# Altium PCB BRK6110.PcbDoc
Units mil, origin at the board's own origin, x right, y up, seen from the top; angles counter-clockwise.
Board outline 4724.41 x 3149.61 mil, 2 copper layers (Top Layer, Bottom Layer), stack 64.8 mil thick; 19 components, 137 nets, 362 pads, 78 vias.
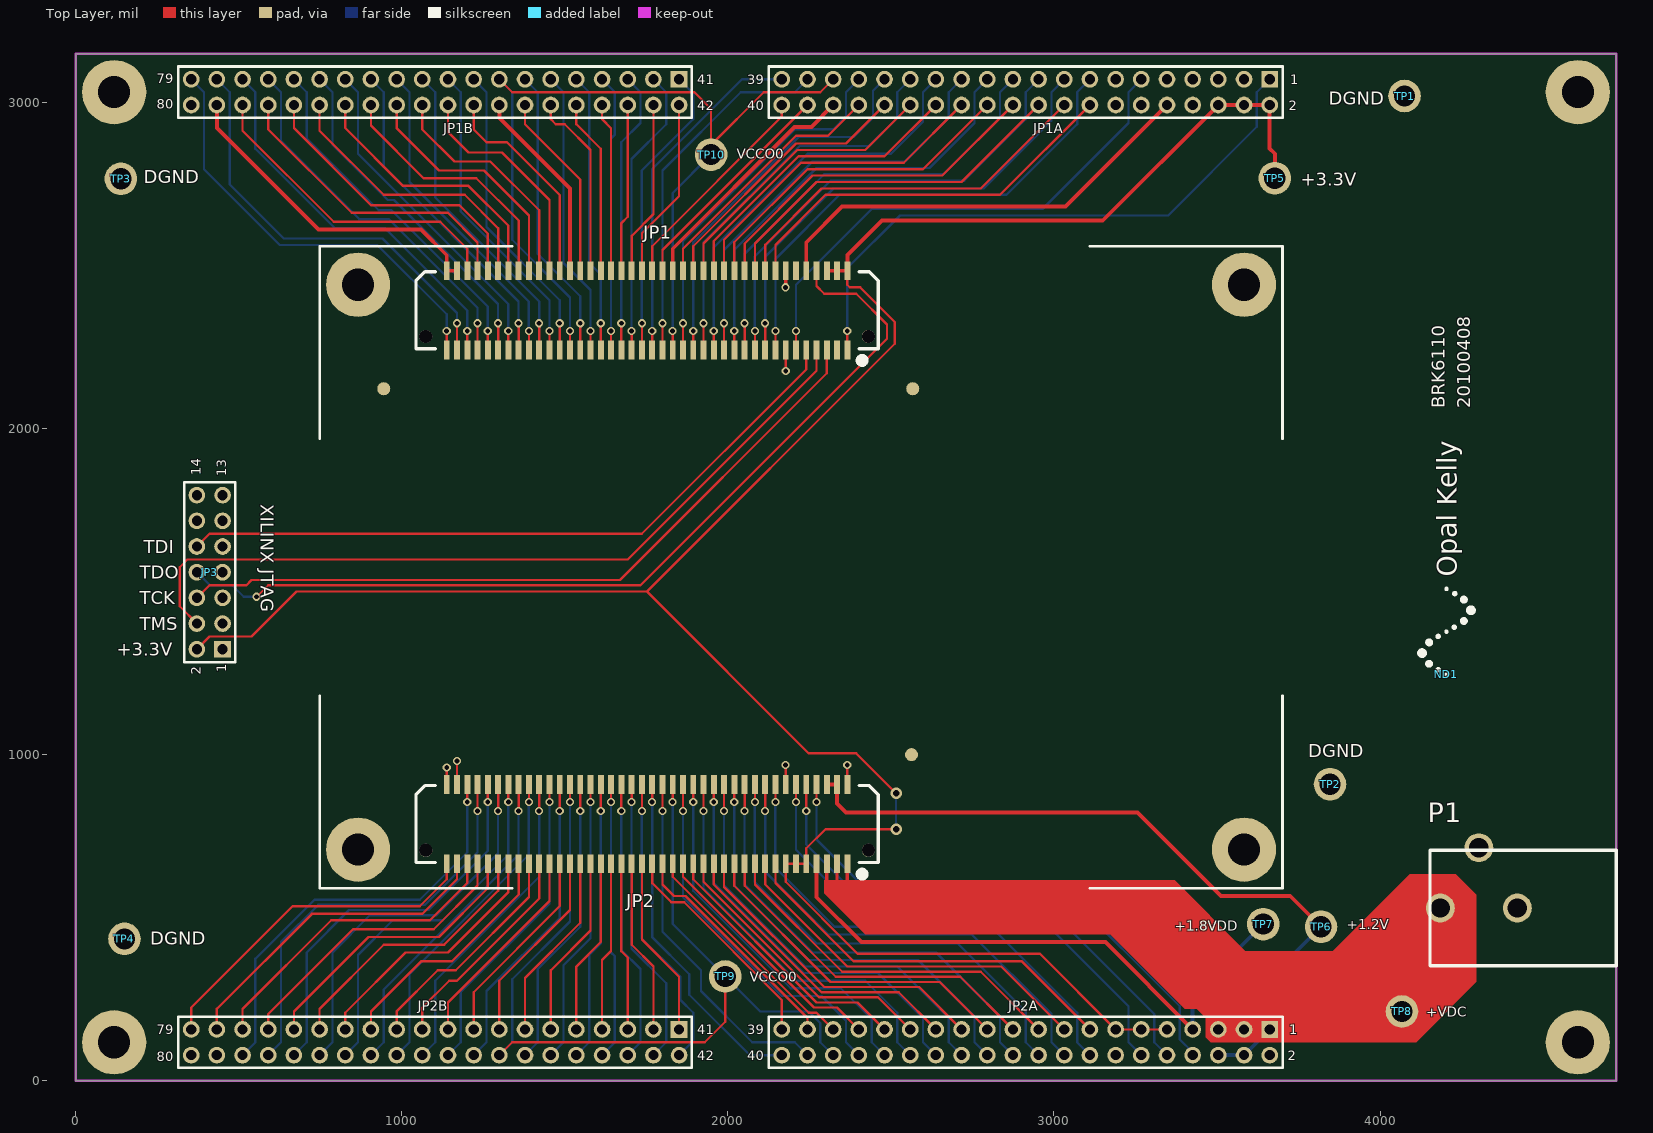
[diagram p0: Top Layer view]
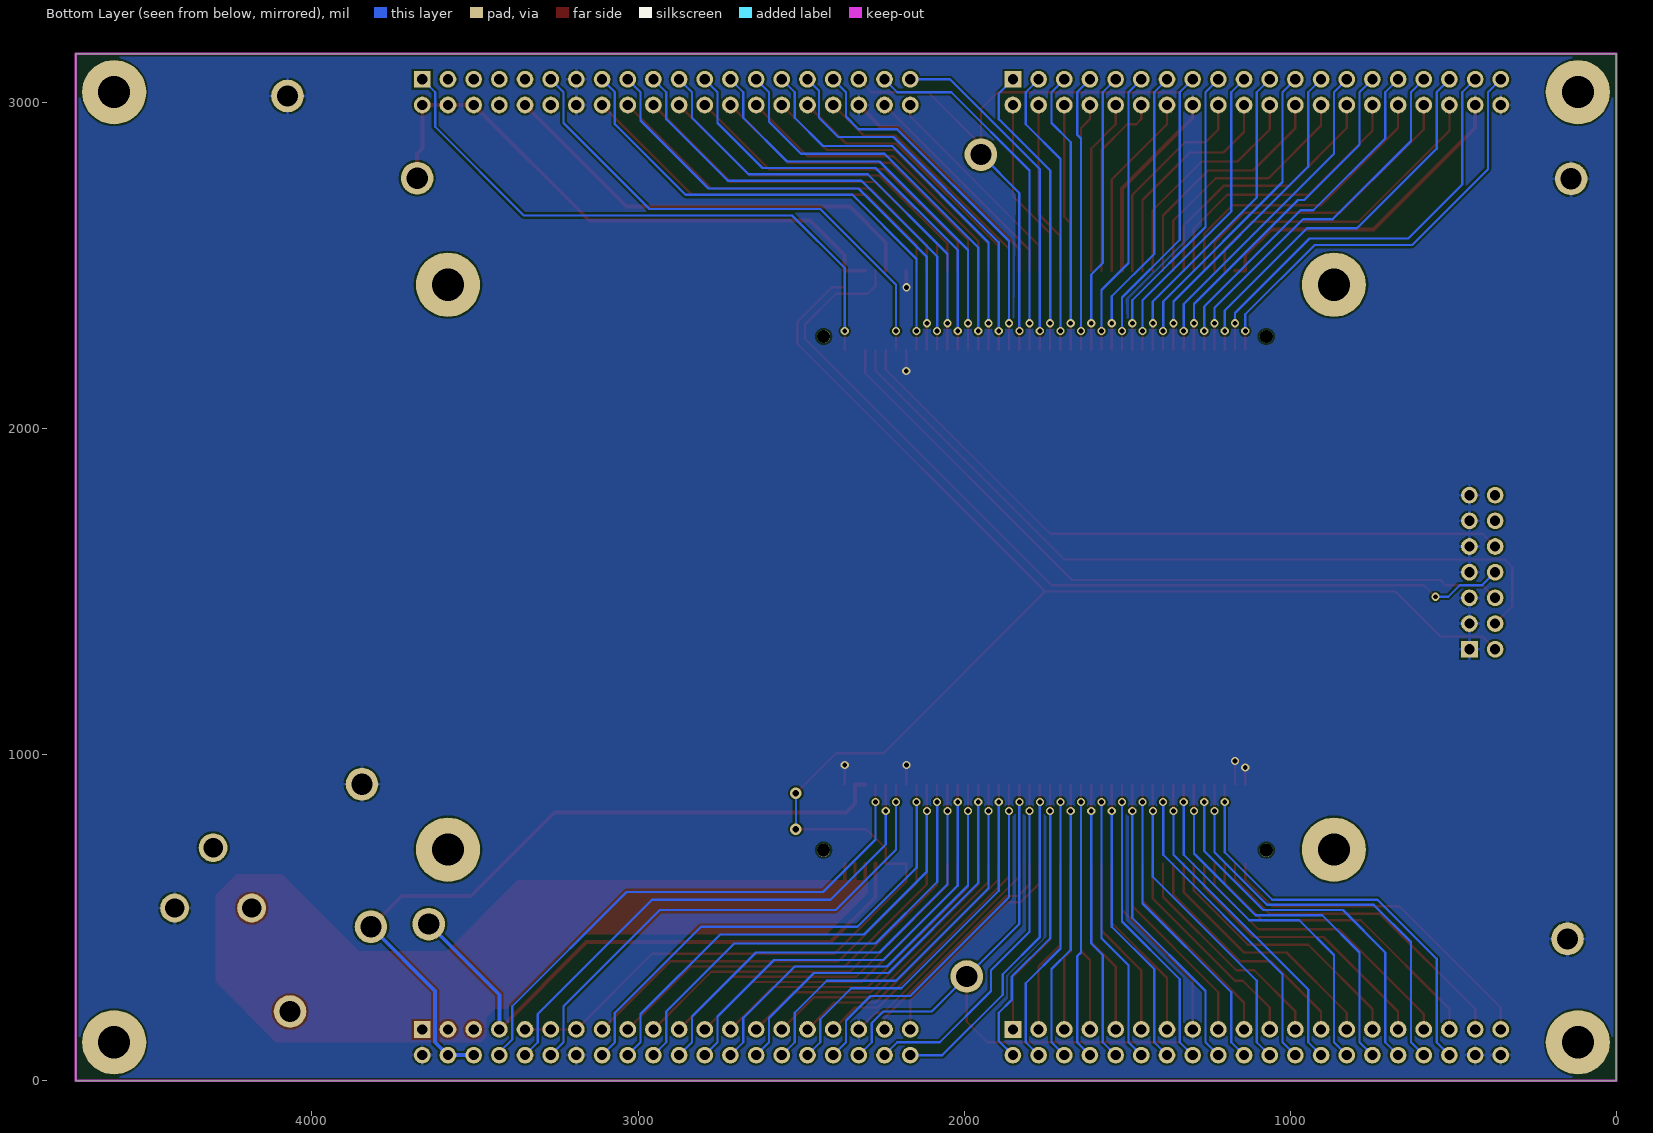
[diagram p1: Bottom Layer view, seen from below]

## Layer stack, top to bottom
Top Layer: signal copper 1.4
Dielectric: core 62, FR-4, Dk 4.8
Bottom Layer: signal copper 1.4

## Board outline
0,0 0,3149.61 4724.41,3149.61 4724.41,0

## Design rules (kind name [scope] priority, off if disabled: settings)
Clearance [All] p1: gap=6
FabricationTestPointUsage TestPointUsage [All] p1: valid=0 allowmultiple=FALSE
FabricationTestpoint Testpoint [All] p1: side=3 testpointundercomponent=TRUE minsize=40 maxsize=100 preferedsize=60 minholesize=0 maxholesize=40 preferedholesize=32 testpointgrid=1 allowsidetop=TRUE allowsidebottom=TRUE usegrid=TRUE gridtolerance=0.01
HoleSize [All] p1: absolutevalues=TRUE maxlimit=236.22 minlimit=15 maxpercent=80.000 minpercent=20.000
PolygonConnect "Via Connect" [IsVia] p1: connectstyle=Direct reliefconductorwidth=10 reliefentries=4 polygonreliefangle="90 Angle"
PolygonConnect [All] p2: connectstyle=Relief reliefconductorwidth=10 reliefentries=4 polygonreliefangle="90 Angle"
RoutingVias [All] p1: holewidth=15 width=25 viastyle="Through Hole" minholewidth=10 minwidth=20 maxholewidth=50 maxwidth=100
SilkscreenOverComponentPads [All] p1: minsilkscreentomaskgap=10
SolderMaskExpansion [All] p1: expansion=4
Width [All] p1: maxlimit=40 minlimit=6 preferedwidth=6 minimp=50.000000 maximp=50.000000 favimp=50.000000
24 further rules are at their usual default settings.

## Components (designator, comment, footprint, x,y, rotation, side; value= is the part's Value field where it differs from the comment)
JP1 "BTE/BSE-040" BTE-040 1752.17,2362.4 r180 top
JP1A "Header 20X2" HDR2X20-2MM 2913.39,3031.5 r180 top
JP1B "Header 20X2" HDR2X20-2MM 1102.36,3031.5 r180 top
JP2 "BTE/BSE-040" BTE-040 1752.17,787.2 r180 top
JP2A "Header 20X2" HDR2X20-2MM 2913.39,118.11 r180 top
JP2B "Header 20X2" HDR2X20-2MM 1102.36,118.11 r180 top
JP3 "JTAGXLNX" HDR2X7-2MM 411.18,1559.53 r90 top
ND1 "OKLOGO" oklogotiny 4203.47,1245.85 r90 top
P1 "DCPOWER" CUI-PJ102A 4723.94,529.61 r90 top
TP1 "TESTPOINT" TP_MED#1 4074.8,3019.69 r180 top
TP2 "TESTPOINT" TP_MED#1 3846.46,909.45 r180 top
TP3 "TESTPOINT" TP_MED#1 138.72,2765.68 r180 top
TP4 "TESTPOINT" TP_MED#1 149.81,435.09 r180 top
TP5 "TESTPOINT" TP_MED#1 3677.17,2767.72 r270 top
TP6 "TESTPOINT" TP_MED#2 3997.32,472.44 r180 top
TP7 "TESTPOINT" TP_MED#1 3641.73,480.31 r180 top
TP8 "TESTPOINT" TP_MED#1 4066.93,212.6 r180 top
TP9 "TESTPOINT" TP_MED#3 1980,320 r180 top
TP10 "TESTPOINT" TP_MED#4 1980,2840 r180 top

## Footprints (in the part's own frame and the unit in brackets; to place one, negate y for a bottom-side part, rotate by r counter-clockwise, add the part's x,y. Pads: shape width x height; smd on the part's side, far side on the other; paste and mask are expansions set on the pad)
BTE-040 [mm] "0.8mm Samtech socket"
  rect 0.46x1.45 smd: 1(-15.6,3.085) 2(-15.6,-3.085) 3(-14.8,3.085) 4(-14.8,-3.085) 5(-14,3.085) 6(-14,-3.085) 7(-13.2,3.085) 8(-13.2,-3.085) 9(-12.4,3.085) 10(-12.4,-3.085) 11(-11.6,3.085) 12(-11.6,-3.085) 13(-10.8,3.085) 14(-10.8,-3.085) 15(-10,3.085) 16(-10,-3.085) 17(-9.2,3.085) 18(-9.2,-3.085) 19(-8.4,3.085) 20(-8.4,-3.085) 21(-7.6,3.085) 22(-7.6,-3.085) 23(-6.8,3.085) 24(-6.8,-3.085) 25(-6,3.085) 26(-6,-3.085) 27(-5.2,3.085) 28(-5.2,-3.085) 29(-4.4,3.085) 30(-4.4,-3.085) 31(-3.6,3.085) 32(-3.6,-3.085) 33(-2.8,3.085) 34(-2.8,-3.085) 35(-2,3.085) 36(-2,-3.085) 37(-1.2,3.085) 38(-1.2,-3.085) 39(-0.4,3.085) 40(-0.4,-3.085) 41(0.4,3.085) 42(0.4,-3.085) 43(1.2,3.085) 44(1.2,-3.085) 45(2,3.085) 46(2,-3.085) 47(2.8,3.085) 48(2.8,-3.085) 49(3.6,3.085) 50(3.6,-3.085) 51(4.4,3.085) 52(4.4,-3.085) 53(5.2,3.085) 54(5.2,-3.085) 55(6,3.085) 56(6,-3.085) 57(6.8,3.085) 58(6.8,-3.085) 59(7.6,3.085) 60(7.6,-3.085) 61(8.4,3.085) 62(8.4,-3.085) 63(9.2,3.085) 64(9.2,-3.085) 65(10,3.085) 66(10,-3.085) 67(10.8,3.085) 68(10.8,-3.085) 69(11.6,3.085) 70(11.6,-3.085) 71(12.4,3.085) 72(12.4,-3.085) 73(13.2,3.085) 74(13.2,-3.085) 75(14,3.085) 76(14,-3.085) 77(14.8,3.085) 78(14.8,-3.085) 79(15.6,3.085) 80(15.6,-3.085)
  round 1.02 hole 1.02: 81(-17.235,2.035) 82(17.235,2.035)
  silkscreen extent -18,-3 18,4.15
CUI-PJ102A [mm] "2.1mm/5.5mm DC power jack"
  round 2.25 hole 1.5: 1(0,13.7) 2(0,7.7) 3(4.7,10.7)
  silkscreen extent -4.5,0 4.5,14.5
HDR2X7-2MM [mm] "2mm 2x7 header"
  rect 1.3x1.3 hole 0.8: 1(-6,-1)
  round 1.3 hole 0.8: 2(-6,1) 3(-4,-1) 4(-4,1) 5(-2,-1) 6(-2,1) 7(0,-1) 8(0,1) 9(2,-1) 10(2,1) 11(4,-1) 12(4,1) 13(6,-1) 14(6,1)
  silkscreen extent -7,-2 7,2
HDR2X20-2MM [mm] "2mm 2x20 header"
  rect 1.3x1.3 hole 0.8: 1(-19,-1)
  round 1.3 hole 0.8: 2(-19,1) 3(-17,-1) 4(-17,1) 5(-15,-1) 6(-15,1) 7(-13,-1) 8(-13,1) 9(-11,-1) 10(-11,1) 11(-9,-1) 12(-9,1) 13(-7,-1) 14(-7,1) 15(-5,-1) 16(-5,1) 17(-3,-1) 18(-3,1) 19(-1,-1) 20(-1,1) 21(1,-1) 22(1,1) 23(3,-1) 24(3,1) 25(5,-1) 26(5,1) 27(7,-1) 28(7,1) 29(9,-1) 30(9,1) 31(11,-1) 32(11,1) 33(13,-1) 34(13,1) 35(15,-1) 36(15,1) 37(17,-1) 38(17,1) 39(19,-1) 40(19,1)
  silkscreen extent -20,-2 20,2
oklogotiny [mil] "Opal Kelly silkscreen logo (50 mil)."
  silkscreen extent -3,-82 266,82
TP_MED#1 [mil] "Testpoint - medium sized"
  round 100 hole 65: 1(0,0)
TP_MED#2 [mil] "Testpoint - medium sized"
  round 100 hole 65: 1(178.43,0)
TP_MED#3 [mil] "Testpoint - medium sized"
  round 100 hole 65: 1(-11.81,0)
TP_MED#4 [mil] "Testpoint - medium sized"
  round 100 hole 65: 1(31.5,0)

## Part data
JP1 JP2: "Header/Socket - 80-pin - 0.80mm"
JP1A JP1B JP2A JP2B: "Header, 20-Pin, Dual row"
JP3: "Xilinx JTAG Header, 7-Pin, Dual row"
ND1: "Opal Kelly PCB Logo"
P1: "DC Power Connector"
TP1 TP2 TP3 TP4 TP5 TP6 TP7 TP8 TP9 TP10: "Testpoint"

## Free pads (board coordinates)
  round 196.85 hole 98.43: 0(118.11,118.11) 0(118.11,3031.5) 0(866.14,708.66) 0(866.14,2440.94) 0(3582.68,708.66) 0(3582.68,2440.94) 0(4606.3,118.11) 0(4606.3,3031.5)
  round 40 smd mask+20: FD1(2566.93,2122.05) FD2(2562.99,1000) FD3(944.88,2122.05)

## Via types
v1: diameter 25, hole 15, Top Layer to Bottom Layer, 76 vias
v2: diameter 35, hole 20, Top Layer to Bottom Layer, 2 vias

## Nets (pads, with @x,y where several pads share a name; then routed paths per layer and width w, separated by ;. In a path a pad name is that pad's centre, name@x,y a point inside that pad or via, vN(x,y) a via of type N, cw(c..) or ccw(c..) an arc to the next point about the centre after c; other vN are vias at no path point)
+1.2VDD: JP2.4 JP2.6 JP2A.4 JP2A.6 TP6.1 | length 2300.8
  Top Layer w12: JP2.6 JP2.4 2334.84,850.2 2362.2,822.83 3255.91,822.83 3511.81,566.93 3724.41,566.93 TP6.1
  Bottom Layer w12: JP2A.6 JP2A.4 3622.05,118.11 3622.05,275.59 TP6.1
+1.8VDD: JP2.7 JP2A.7 TP7.1 | length 1836.7
  Top Layer w12: JP2.7 2271.85,562.8 2409.45,425.2 3157.48,425.2 JP2A.7
  Bottom Layer w12: JP2A.7 3425.2,263.78 TP7.1
+3.3VDD: JP1.2 JP1.4 JP1.6 JP1A.2 JP1A.4 JP1A.6 JP2.9 JP2.11 JP2.13 JP2A.9 JP2A.11 JP2A.13 JP3.2 TP5.1 | length 7610.3
  Top Layer w7: JP3.2 410.71,1362.2 539.37,1362.2 677.17,1500 1751.97,1500 ; JP1.2 2366.34,2440.75 2374.02,2433.07 2405.51,2433.07 2511.81,2326.77 2511.81,2259.84 1751.97,1500 ; v2(2515.75,771.65) 2299.21,771.65 2240.35,712.8 JP2.9 JP2.11 JP2.13 2177.36,610.04 2397.64,389.76 2956.69,389.76 JP2A.13 JP2A.11 JP2A.9 ; v2(2515.75,881.89) 2393.7,1003.94 2248.03,1003.94 1751.97,1500
  Top Layer w12: JP1.6 JP1.4 JP1.2 2366.34,2531.69 2472.44,2637.8 3149.61,2637.8 JP1A.6 JP1A.4 JP1A.2 3661.42,2858.27 3677.17,2842.52 TP5.1
  Bottom Layer w7: v2(2515.75,771.65) v2(2515.75,881.89)
+VCCO0: JP2.36 JP2.56 JP2A.36 JP2B.16 TP9.1 | length 2914.8
  Top Layer w7: JP2B.16 1338.58,118.11 1929.13,118.11 1991.81,180.79 TP9.1 ; v1(1515.75,854.33) 1515.94,854.53 JP2.56 ; v1(1830.71,854.33) 1830.91,854.53 JP2.36
  Bottom Layer w7: JP2B.16 1338.58,118.11 1338.58,311.02 1515.75,488.19 v1(1515.75,854.33) ; v1(1830.71,854.33) 1830.71,481.1 TP9.1 2099.21,212.6 2248.03,212.6 2283.46,177.17 2283.46,118.11 JP2A.36
+VCCO1: JP1.35 JP1.55 JP1A.35 JP1B.15 TP10.1 | length 2852.6
  Top Layer w7: JP1B.15 1338.58,3031.5 1897.64,3031.5 1948.5,2980.63 TP10.1@1948.5,2869.76 ; v1(1515.75,2299.21) 1515.94,2299.02 JP1.55 ; v1(1830.71,2299.21) 1830.91,2299.02 JP1.35 ; TP10.1 TP10.1@1948.5,2869.76 ; JP1A.35 2283.46,3031.5 2110.24,3031.5 TP10.1@1948.5,2869.76
  Bottom Layer w7: JP1B.15 1338.58,3031.5 1338.58,2578.74 1515.75,2401.57 v1(1515.75,2299.21) ; v1(1830.71,2299.21) 1830.71,2722.2 TP10.1
+VDC: JP2.1 JP2.3 JP2.5 JP2A.1 JP2A.3 JP2A.5 P1.1 TP8.1 | length 205.7
  Top Layer w10: 2303.35,582.48 JP2.5 ; 2334.84,606.5 JP2.3 ; 2366.34,602.56 JP2.1
DGND: JP1.13 JP1.14 JP1.36 JP1.56 JP1.78 JP1.80 JP1A.13 JP1A.14 JP1A.36 JP1B.16 JP1B.38 JP1B.40 JP2.2 JP2.14 JP2.35 JP2.55 JP2.78 JP2.80 JP2A.2 JP2A.14 JP2A.35 JP2B.15 JP2B.38 JP2B.40 JP3.1 JP3.3 JP3.5 JP3.7 JP3.9 JP3.11 JP3.13 P1.2 TP1.1 TP2.1 TP3.1 TP4.1 | length 4038.5
  Top Layer w7: JP2.80 v1(1137.99,960.63) ; JP2.78 v1(1169.49,980.31) ; JP2B.15 1299.21,307.09 1515.94,523.82 JP2.55 ; JP2.35 1830.91,625.79 2248.03,208.66 2271.65,208.66 JP2A.35 ; v1(2177.17,968.5) 2177.36,968.31 JP2.14 ; v1(2177.17,2433.07) v1@2177.36,2433.27 ; v1(2177.36,2176.97) JP1.13 ; v1(2366.14,968.5) 2366.34,968.31 JP2.2
  Top Layer w12: JP1B.38 433.07,2921.26 744.09,2610.24 1059.06,2610.24 1137.99,2531.3 JP1.80 JP1.78 ; JP1B.16 1299.21,2952.76 1515.94,2736.02 JP1.56 ; JP1.36 1830.91,2551.38 2204.72,2925.2 2255.9,2925.2 JP1A.36 ; v1@2177.36,2433.27 JP1.14
JP2_8: JP2.8 JP2A.8 | length 1660.7
  Top Layer w7: v1(2271.65,854.33) 2271.85,854.53 JP2.8
  Bottom Layer w7: v1(2271.65,854.33) 2271.65,740.16 2433.07,578.74 3035.43,578.74 3385.83,228.35 3385.83,126.67 3425.2,87.3 JP2A.8
JP2_10: JP2.10 JP2A.10 | length 1608.8
  Top Layer w7: v1(2240.16,826.77) 2240.35,826.97 JP2.10
  Bottom Layer w7: v1(2240.16,826.77) 2240.16,724.41 2409.45,555.12 2956.69,555.12 3307.09,204.72 3307.09,118.11 JP2A.10
JP2_12: JP2.12 JP2A.12 | length 1584.6
  Top Layer w7: v1(2208.66,854.33) 2208.86,854.53 JP2.12
  Bottom Layer w7: v1(2208.66,854.33) 2208.66,708.66 2393.7,523.62 2933.07,523.62 3228.35,228.35 3228.35,118.11 JP2A.12
JP2_15: JP2.15 JP2A.15 | length 1209.8
  Top Layer w7: JP2.15 2145.87,606.1 2385.83,366.14 2901.57,366.14 JP2A.15
JP2_16: JP2.16 JP2A.16 | length 1510.9
  Top Layer w7: v1(2145.67,854.33) 2145.87,854.53 JP2.16
  Bottom Layer w7: v1(2145.67,854.33) 2145.67,653.54 2326.77,472.44 2807.09,472.44 3070.87,208.66 3070.87,118.11 JP2A.16
JP2_17: JP2.17 JP2A.17 | length 1164.9
  Top Layer w7: JP2.17 2114.37,602.17 2366.14,350.39 2838.58,350.39 JP2A.17
JP2_18: JP2.18 JP2A.18 | length 1468.3
  Top Layer w7: v1(2114.17,826.77) 2114.37,826.97 JP2.18
  Bottom Layer w7: v1(2114.17,826.77) 2114.17,641.73 2307.09,448.82 2748.03,448.82 2992.13,204.72 2992.13,118.11 JP2A.18
JP2_19: JP2.19 JP2A.19 | length 1117.7
  Top Layer w7: JP2.19 2082.87,602.17 2350.39,334.65 2775.59,334.65 JP2A.19
JP2_20: JP2.20 JP2A.20 | length 1444.1
  Top Layer w7: v1(2082.68,854.33) 2082.87,854.53 JP2.20
  Bottom Layer w7: v1(2082.68,854.33) 2082.68,610.24 2271.65,421.26 2704.72,421.26 2913.39,212.6 2913.39,118.11 JP2A.20
JP2_21: JP2.21 JP2A.21 | length 1072.7
  Top Layer w7: JP2.21 2051.38,598.23 2330.71,318.9 2712.6,318.9 JP2A.21
JP2_22: JP2.22 JP2A.22 | length 1392.2
  Top Layer w7: v1(2051.18,826.77) 2051.38,826.97 JP2.22
  Bottom Layer w7: v1(2051.18,826.77) 2051.18,602.36 2259.84,393.7 2637.8,393.7 2834.65,196.85 2834.65,118.11 JP2A.22
JP2_23: JP2.23 JP2A.23 | length 1025.5
  Top Layer w7: JP2.23 2019.88,598.23 2314.96,303.15 2649.61,303.15 JP2A.23
JP2_24: JP2.24 JP2A.24 | length 1347.3
  Top Layer w7: v1(2019.69,854.33) 2019.88,854.53 JP2.24
  Bottom Layer w7: v1(2019.69,854.33) 2019.69,598.43 2248.03,370.08 2582.68,370.08 2755.91,196.85 2755.91,118.11 JP2A.24
JP2_25: JP2.25 JP2A.25 | length 980.5
  Top Layer w7: JP2.25 1988.39,594.29 2295.28,287.4 2586.61,287.4 JP2A.25
JP2_26: JP2.26 JP2A.26 | length 1297.7
  Top Layer w7: v1(1988.19,826.77) 1988.39,826.97 JP2.26
  Bottom Layer w7: v1(1988.19,826.77) 1988.19,598.43 2236.22,350.39 2519.69,350.39 2677.17,192.91 2677.17,118.11 JP2A.26
JP2_27: JP2.27 JP2A.27 | length 928.7
  Top Layer w7: JP2.27 1956.89,602.17 2287.4,271.65 2523.62,271.65 JP2A.27
JP2_28: JP2.28 JP2A.28 | length 1245.9
  Top Layer w7: v1(1956.69,854.33) 1956.89,854.53 JP2.28
  Bottom Layer w7: v1(1956.69,854.33) 1956.69,606.3 2232.28,330.71 2460.63,330.71 2598.43,192.91 2598.43,118.11 JP2A.28
JP2_29: JP2.29 JP2A.29 | length 876.8
  Top Layer w7: JP2.29 1925.39,610.04 2279.53,255.91 2460.63,255.91 JP2A.29
JP2_30: JP2.30 JP2A.30 | length 1217.1
  Top Layer w7: v1(1925.2,826.77) 1925.39,826.97 JP2.30
  Bottom Layer w7: v1(1925.2,826.77) 1925.2,590.55 2208.66,307.09 2421.26,307.09 2519.69,208.66 2519.69,118.11 JP2A.30
JP2_31: JP2.31 JP2A.31 | length 825
  Top Layer w7: JP2.31 1893.9,617.91 2271.65,240.16 2397.64,240.16 JP2A.31
JP2_32: JP2.32 JP2A.32 | length 1162.9
  Top Layer w7: v1(1893.7,854.33) 1893.9,854.53 JP2.32
  Bottom Layer w7: v1(1893.7,854.33) 1893.7,582.68 2192.91,283.46 2346.46,283.46 2440.94,188.98 2440.94,118.11 JP2A.32
JP2_33: JP2.33 JP2A.33 | length 773.1
  Top Layer w7: JP2.33 1862.4,625.79 2263.78,224.41 2334.64,224.41 JP2A.33
JP2_34: JP2.34 JP2A.34 | length 1124.9
  Top Layer w7: v1(1862.2,826.77) 1862.4,826.97 JP2.34
  Bottom Layer w7: v1(1862.2,826.77) 1862.2,562.99 2165.35,259.84 2287.4,259.84 2362.2,185.04 2362.2,118.11 JP2A.34
JP2_37: JP2.37 JP2A.37 | length 713.2
  Top Layer w7: JP2.37 1799.41,602.16 1834.64,566.93 1870.08,566.93 2244.09,192.91 JP2A.37
JP2_38: JP2.38 JP2A.38 | length 1090.4
  Top Layer w7: v1(1799.21,826.77) 1799.41,826.97 JP2.38
  Bottom Layer w7: v1(1799.21,826.77) 1799.21,456.69 1917.32,338.58 1917.32,275.59 2074.8,118.11 2204.72,118.11 JP2A.38
JP2_39: JP2.39 JP2A.39 | length 696
  Top Layer w7: JP2.39 1767.91,606.1 1826.77,547.24 1866.14,547.24 2165.35,248.03 JP2A.39
JP2_40: JP2.40 JP2A.40 | length 1052.4
  Top Layer w7: v1(1767.72,854.33) 1767.91,854.53 JP2.40
  Bottom Layer w7: v1(1767.72,854.33) 1767.72,440.94 1881.89,326.77 1881.89,263.78 2066.93,78.74 JP2A.40
JP2_41: JP2.41 JP2B.1 | length 555.5
  Top Layer w7: JP2.41 1736.42,432.87 1850.39,318.9 JP2B.1
JP2_42: JP2.42 JP2B.2 | length 913.2
  Top Layer w7: v1(1736.22,826.77) 1736.42,826.97 JP2.42
  Bottom Layer w7: v1(1736.22,826.77) 1736.22,437.01 1854.33,318.9 1854.33,248.03 1893.7,208.66 1893.7,122.05 JP2B.2
JP2_43: JP2.43 JP2B.3 | length 535.9
  Top Layer w7: JP2.43 1704.92,417.13 1771.65,350.39 JP2B.3
JP2_44: JP2.44 JP2B.4 | length 890.3
  Top Layer w7: v1(1704.72,854.33) 1704.92,854.53 JP2.44
  Bottom Layer w7: v1(1704.72,854.33) 1704.72,405.51 1811.02,299.21 1811.02,118.11 JP2B.4
JP2_45: JP2.45 JP2B.5 | length 516.3
  Top Layer w7: JP2.45 1673.43,397.44 1692.91,377.95 JP2B.5
JP2_46: JP2.46 JP2B.6 | length 870.8
  Top Layer w7: v1(1673.23,826.77) 1673.43,826.97 JP2.46
  Bottom Layer w7: v1(1673.23,826.77) 1673.23,401.57 1732.28,342.52 1732.28,118.11 JP2B.6
JP2_47: JP2.47 JP2B.7 | length 519.8
  Top Layer w7: JP2B.7 1614.17,370.08 1641.93,397.83 JP2.47
JP2_48: JP2.48 JP2B.8 | length 851.2
  Top Layer w7: v1(1641.73,854.33) 1641.93,854.53 JP2.48
  Bottom Layer w7: JP2B.8 1653.54,118.11 1653.54,381.89 1641.73,393.7 v1(1641.73,854.33)
JP2_49: JP2.49 JP2B.9 | length 539.3
  Top Layer w7: JP2B.9 1535.43,350.39 1610.43,425.39 JP2.49
JP2_50: JP2.50 JP2B.10 | length 861
  Top Layer w7: v1(1610.24,826.77) 1610.43,826.97 JP2.50
  Bottom Layer w7: JP2B.10 1574.8,118.11 1574.8,385.83 1610.24,421.26 v1(1610.24,826.77)
JP2_51: JP2.51 JP2B.11 | length 558.9
  Top Layer w7: JP2B.11 1456.69,338.58 1578.94,460.83 JP2.51
JP2_52: JP2.52 JP2B.12 | length 880.6
  Top Layer w7: v1(1578.74,854.33) 1578.94,854.53 JP2.52
  Bottom Layer w7: JP2B.12 1496.06,118.11 1496.06,354.33 1578.74,437.01 v1(1578.74,854.33)
JP2_53: JP2.53 JP2B.13 | length 578.5
  Top Layer w7: JP2B.13 1377.95,314.96 1547.44,484.45 JP2.53
JP2_54: JP2.54 JP2B.14 | length 900.1
  Top Layer w7: v1(1547.24,826.77) 1547.44,826.97 JP2.54
  Bottom Layer w7: JP2B.14 1417.32,118.11 1417.32,342.52 1547.24,472.44 v1(1547.24,826.77)
JP2_57: JP2.57 JP2B.17 | length 617.6
  Top Layer w7: JP2B.17 1220.47,271.65 1484.45,535.63 JP2.57
JP2_58: JP2.58 JP2B.18 | length 939.3
  Top Layer w7: v1(1484.25,826.77) 1484.45,826.97 JP2.58
  Bottom Layer w7: JP2B.18 1259.84,118.11 1259.84,275.59 1484.25,500 v1(1484.25,826.77)
JP2_59: JP2.59 JP2B.19 | length 637.2
  Top Layer w7: JP2B.19 1141.73,240.16 1452.95,551.38 JP2.59
JP2_60: JP2.60 JP2B.20 | length 958.8
  Top Layer w7: v1(1452.76,854.33) 1452.95,854.53 JP2.60
  Bottom Layer w7: JP2B.20 1181.1,118.11 1181.1,271.65 1452.76,543.31 v1(1452.76,854.33)
JP2_61: JP2.61 JP2B.21 | length 670.6
  Top Layer w7: JP2B.21 1062.99,224.41 1145.67,307.09 1169.29,307.09 1421.46,559.25 JP2.61
JP2_62: JP2.62 JP2B.22 | length 978.4
  Top Layer w7: v1(1421.26,826.77) 1421.46,826.97 JP2.62
  Bottom Layer w7: JP2B.22 1102.36,118.11 1102.36,307.09 1421.26,625.98 v1(1421.26,826.77)
JP2_63: JP2.63 JP2B.23 | length 708.6
  Top Layer w7: JP2B.23 984.25,212.6 1110.24,338.58 1165.35,338.58 1389.96,563.19 JP2.63
JP2_64: JP2.64 JP2B.24 | length 998
  Top Layer w7: v1(1389.76,854.33) 1389.96,854.53 JP2.64
  Bottom Layer w7: JP2B.24 1023.62,118.11 1023.62,326.77 1389.76,692.91 v1(1389.76,854.33)
JP2_65: JP2.65 JP2B.25 | length 751.2
  Top Layer w7: JP2B.25 905.51,212.6 1059.06,366.14 1153.54,366.14 1358.46,571.06 JP2.65
JP2_66: JP2.66 JP2B.26 | length 1017.5
  Top Layer w7: v1(1358.27,826.77) 1358.46,826.97 JP2.66
  Bottom Layer w7: JP2B.26 944.88,118.11 944.88,279.53 1358.27,692.91 v1(1358.27,826.77)
JP2_67: JP2.67 JP2B.27 | length 791.6
  Top Layer w7: JP2B.27 826.77,208.66 1011.81,393.7 1141.73,393.7 1326.97,578.94 JP2.67
JP2_68: JP2.68 JP2B.28 | length 1127.1
  Top Layer w7: v1(1326.77,854.33) 1326.97,854.53 JP2.68
  Bottom Layer w7: JP2B.28 866.14,118.11 866.14,385.83 972.44,492.13 1125.98,492.13 1326.77,692.91 v1(1326.77,854.33)
JP2_69: JP2.69 JP2B.29 | length 843.4
  Top Layer w7: JP2B.29 748.03,220.47 944.88,417.32 1129.92,417.32 1295.47,582.87 JP2.69
JP2_70: JP2.70 JP2B.30 | length 1176.6
  Top Layer w7: v1(1295.28,826.77) 1295.47,826.97 JP2.70
  Bottom Layer w7: JP2B.30 787.4,118.11 787.4,393.7 901.57,507.87 1106.3,507.87 1295.28,696.85 v1(1295.28,826.77)
JP2_71: JP2.71 JP2B.31 | length 881.4
  Top Layer w7: JP2B.31 669.29,212.6 897.64,440.94 1114.17,440.94 1263.98,590.75 JP2.71
JP2_72: JP2.72 JP2B.32 | length 1219.2
  Top Layer w7: v1(1263.78,854.33) 1263.98,854.53 JP2.72
  Bottom Layer w7: JP2B.32 708.66,118.11 708.66,393.7 838.58,523.62 1082.68,523.62 1263.78,704.72 v1(1263.78,854.33)
JP2_73: JP2.73 JP2B.33 | length 919.5
  Top Layer w7: JP2B.33 590.55,204.72 850.39,464.57 1098.43,464.57 1232.48,598.62 JP2.73
JP2_74: JP2.74 JP2B.34 | length 1287.2
  Top Layer w7: v1(1232.28,826.77) 1232.48,826.97 JP2.74
  Bottom Layer w7: JP2B.34 629.92,118.11 629.92,425.2 744.09,539.37 1070.87,539.37 1232.28,700.79 v1(1232.28,826.77)
JP2_75: JP2.75 JP2B.35 | length 971.3
  Top Layer w7: JP2B.35 511.81,220.47 783.46,492.13 1086.61,492.13 1200.98,606.5 JP2.75
JP2_76: JP2.76 JP2B.36 | length 1304.5
  Top Layer w7: v1(1200.79,854.33) 1200.98,854.53 JP2.76
  Bottom Layer w7: JP2B.36 551.18,118.11 551.18,374.02 732.28,555.12 1055.12,555.12 1200.79,700.79 v1(1200.79,854.33)
JP2_77: JP2.77 JP2B.37 | length 1011.6
  Top Layer w7: JP2B.37 433.07,220.47 724.41,511.81 1062.99,511.81 1169.49,618.31 JP2.77
JP2_79: JP2.79 JP2B.39 | length 1061.2
  Top Layer w7: JP2B.39 354.33,224.41 665.35,535.43 1055.12,535.43 1137.99,618.31 JP2.79
JP3_1: JP1.1 JP1A.1 | length 1848.5
  Top Layer w7: v1(2366.14,2299.21) 2366.34,2299.02 JP1.1
  Bottom Layer w7: v1(2366.14,2299.21) 2366.14,2492.13 2527.56,2653.54 3350.39,2653.54 3622.05,2925.2 3622.05,3031.5 JP1A.1
JP3_11: JP1.11 JP1A.11 | length 1575.4
  Top Layer w7: v1(2208.66,2299.21) 2208.86,2299.02 JP1.11
  Bottom Layer w7: v1(2208.66,2299.21) 2208.66,2440.94 2440.94,2673.23 2964.57,2673.23 3228.35,2937.01 3228.35,3031.5 JP1A.11
JP3_15: JP1.15 JP1A.15 | length 1529.2
  Top Layer w7: JP1.15 v1(2145.87,2299.02)
  Bottom Layer w7: v1(2145.87,2299.02) 2145.87,2519.88 2342.52,2716.54 2854.33,2716.54 3070.87,2933.07 3070.87,3031.5 JP1A.15
JP3_16: JP1.16 JP1A.16 | length 1221.4
  Top Layer w7: JP1.16 2145.87,2563.19 2299.21,2716.54 2834.65,2716.54 JP1A.16
JP3_17: JP1.17 JP1A.17 | length 1479.1
  Top Layer w7: v1(2114.17,2322.83) 2114.37,2322.64 JP1.17
  Bottom Layer w7: v1(2114.17,2322.83) 2114.17,2526.37 2324.02,2736.22 2783.46,2736.22 2992.13,2944.88 2992.13,3031.5 JP1A.17
JP3_18: JP1.18 JP1A.18 | length 1174.1
  Top Layer w7: JP1.18 2114.37,2563.19 2287.4,2736.22 2775.59,2736.22 JP1A.18
JP3_19: JP1.19 JP1A.19 | length 1430.3
  Top Layer w7: v1(2082.68,2299.21) 2082.87,2299.02 JP1.19
  Bottom Layer w7: v1(2082.68,2299.21) 2082.68,2527.56 2314.96,2759.84 2724.41,2759.84 2913.39,2948.82 2913.39,3031.5 JP1A.19
JP3_20: JP1.20 JP1A.20 | length 1129.2
  Top Layer w7: JP1.20 2082.87,2567.13 2271.65,2755.91 2716.54,2755.91 JP1A.20
JP3_21: JP1.21 JP1A.21 | length 1385.3
  Top Layer w7: v1(2051.18,2322.83) 2051.38,2322.64 JP1.21
  Bottom Layer w7: v1(2051.18,2322.83) 2051.18,2535.43 2295.28,2779.53 2661.42,2779.53 2834.65,2952.76 2834.65,3031.5 JP1A.21
JP3_22: JP1.22 JP1A.22 | length 1081.9
  Top Layer w7: JP1.22 2051.38,2567.13 2259.84,2775.59 2657.48,2775.59 JP1A.22
JP3_23: JP1.23 JP1A.23 | length 1354.2
  Top Layer w7: v1(2019.69,2299.21) 2019.88,2299.02 JP1.23
  Bottom Layer w7: v1(2019.69,2299.21) 2019.69,2547.24 2271.65,2799.21 2618.11,2799.21 2755.91,2937.01 2755.91,3031.5 JP1A.23
JP3_24: JP1.24 JP1A.24 | length 1037
  Top Layer w7: JP1.24 2019.88,2571.06 2244.09,2795.28 2598.43,2795.28 JP1A.24
JP3_25: JP1.25 JP1A.25 | length 1297.7
  Top Layer w7: v1(1988.19,2322.83) 1988.39,2322.64 JP1.25
  Bottom Layer w7: v1(1988.19,2322.83) 1988.19,2547.24 2259.84,2818.9 2543.31,2818.9 2677.17,2952.76 2677.17,3031.5 JP1A.25
JP3_26: JP1.26 JP1A.26 | length 994.4
  Top Layer w7: JP1.26 1988.39,2578.94 2224.41,2814.96 2539.37,2814.96 JP1A.26
JP3_27: JP1.27 JP1A.27 | length 1262
  Top Layer w7: v1(1956.69,2299.21) 1956.89,2299.02 JP1.27
  Bottom Layer w7: v1(1956.69,2299.21) 1956.69,2555.12 2244.09,2842.52 2500,2842.52 2598.43,2940.94 2598.43,3031.5 JP1A.27
JP3_28: JP1.28 JP1A.28 | length 944.8
  Top Layer w7: JP1.28 1956.89,2575 2216.54,2834.65 2480.32,2834.65 JP1A.28
JP3_29: JP1.29 JP1A.29 | length 1217.1
  Top Layer w7: v1(1925.2,2322.83) 1925.39,2322.64 JP1.29
  Bottom Layer w7: v1(1925.2,2322.83) 1925.2,2570.87 2220.47,2866.14 2433.07,2866.14 2519.69,2952.76 2519.69,3031.5 JP1A.29
JP3_30: JP1.30 JP1A.30 | length 893
  Top Layer w7: JP1.30 1925.39,2567.13 2212.6,2854.33 2421.26,2854.33 JP1A.30
JP3_31: JP1.31 JP1A.31 | length 1172.2
  Top Layer w7: v1(1893.7,2299.21) 1893.9,2299.02 JP1.31
  Bottom Layer w7: v1(1893.7,2299.21) 1893.7,2570.87 2216.54,2893.7 2385.83,2893.7 2444.88,2952.76 2444.88,3035.43 JP1A.31
JP3_32: JP1.32 JP1A.32 | length 841.1
  Top Layer w7: JP1.32 1893.9,2559.25 2208.66,2874.02 2362.21,2874.02 JP1A.32
JP3_33: JP1.33 JP1A.33 | length 1122.6
  Top Layer w7: v1(1862.2,2322.83) 1862.4,2322.64 JP1.33
  Bottom Layer w7: v1(1862.2,2322.83) 1862.2,2574.8 2204.72,2917.32 2322.83,2917.32 2362.2,2956.69 2362.2,3031.5 JP1A.33
JP3_34: JP1.34 JP1A.34 | length 789.3
  Top Layer w7: JP1.34 1862.4,2551.38 2208.66,2897.64 2307.09,2897.64 JP1A.34
JP3_37: JP1.37 JP1A.37 | length 1111.1
  Top Layer w7: v1(1799.21,2322.83) 1799.41,2322.64 JP1.37
  Bottom Layer w7: v1(1799.21,2322.83) 1799.21,2791.34 2039.37,3031.5 2204.72,3031.5 JP1A.37
JP3_38: JP1.38 JP1A.38 | length 692.5
  Top Layer w7: JP1.38 1799.41,2547.44 JP1A.38
JP3_39: JP1.39 JP1A.39 | length 1066
  Top Layer w7: JP1.39 v1(1767.91,2299.02)
  Bottom Layer w7: v1(1767.91,2299.02) 1767.91,2795.47 2043.31,3070.87 JP1A.39
JP3_40: JP1.40 JP1A.40 | length 672.9
  Top Layer w7: JP1.40 1767.91,2559.25 2165.35,2956.69 JP1A.40
JP3_41: JP1.41 JP1B.1 | length 913.2
  Top Layer w7: v1(1736.22,2322.83) 1736.42,2322.64 JP1.41
  Bottom Layer w7: v1(1736.22,2322.83) 1736.22,2791.34 1893.7,2948.82 1893.7,3027.56 JP1B.1
JP3_42: JP1.42 JP1B.2 | length 555.5
  Top Layer w7: JP1.42 1736.42,2598.62 1850.39,2712.6 JP1B.2
JP3_43: JP1.43 JP1B.3 | length 890.3
  Top Layer w7: v1(1704.72,2299.21) 1704.92,2299.02 JP1.43
  Bottom Layer w7: v1(1704.72,2299.21) 1704.72,2826.77 1811.02,2933.07 1811.02,3031.5 JP1B.3
JP3_44: JP1.44 JP1B.4 | length 535.9
  Top Layer w7: JP1.44 1704.92,2590.75 1771.65,2657.48 JP1B.4
JP3_45: JP1.45 JP1B.5 | length 870.8
  Top Layer w7: v1(1673.23,2322.83) 1673.43,2322.64 JP1.45
  Bottom Layer w7: v1(1673.23,2322.83) 1673.23,2877.95 1732.28,2937.01 1732.28,3031.5 JP1B.5
JP3_46: JP1.46 JP1B.6 | length 516.3
  Top Layer w7: JP1.46 1673.43,2630.12 1692.91,2649.61 JP1B.6
JP3_47: JP1.47 JP1B.7 | length 851.2
  Top Layer w7: v1(1641.73,2299.21) 1641.93,2299.02 JP1.47
  Bottom Layer w7: JP1B.7 1653.54,3031.49 1653.54,2901.57 1641.73,2889.76 v1(1641.73,2299.21)
JP3_48: JP1.48 JP1B.8 | length 519.8
  Top Layer w7: JP1B.8 1614.17,2948.82 1641.93,2921.06 JP1.48
JP3_49: JP1.49 JP1B.9 | length 861
  Top Layer w7: v1(1610.24,2322.83) 1610.43,2322.64 JP1.49
  Bottom Layer w7: JP1B.9 1574.8,3031.5 1574.8,2507.87 1610.24,2472.44 v1(1610.24,2322.83)
JP3_50: JP1.50 JP1B.10 | length 539.3
  Top Layer w7: JP1B.10 1535.43,2933.07 1610.43,2858.07 JP1.50
JP3_51: JP1.51 JP1B.11 | length 880.6
  Top Layer w7: v1(1578.74,2299.21) 1578.94,2299.02 JP1.51
  Bottom Layer w7: JP1B.11 1496.06,3031.5 1496.06,2507.87 1578.74,2425.2 v1(1578.74,2299.21)
JP3_52: JP1.52 JP1B.12 | length 575
  Top Layer w7: JP1B.12 1456.69,2948.82 1472.44,2933.07 1500,2933.07 1578.94,2854.13 JP1.52
JP3_53: JP1.53 JP1B.13 | length 900.1
  Top Layer w7: v1(1547.24,2322.83) 1547.44,2322.64 JP1.53
  Bottom Layer w7: JP1B.13 1417.32,3031.5 1417.32,2535.43 1547.24,2405.51 v1(1547.24,2322.83)
JP3_54: JP1.54 JP1B.14 | length 578.5
  Top Layer w7: JP1B.14 1377.95,2933.07 1547.44,2763.58 JP1.54
JP3_57: JP1.57 JP1B.17 | length 939.3
  Top Layer w7: v1(1484.25,2322.83) 1484.45,2322.64 JP1.57
  Bottom Layer w7: JP1B.17 1259.84,3031.5 1259.84,2618.11 1484.25,2393.7 v1(1484.25,2322.83)
JP3_58: JP1.58 JP1B.18 | length 654.5
  Top Layer w7: JP1B.18 1220.47,2917.32 1259.84,2877.95 1322.83,2877.95 1484.45,2716.34 JP1.58
JP3_59: JP1.59 JP1B.19 | length 958.8
  Top Layer w7: v1(1452.76,2299.21) 1452.95,2299.02 JP1.59
  Bottom Layer w7: JP1B.19 1181.1,3031.5 1181.1,2665.35 1452.76,2393.7 v1(1452.76,2299.21)
JP3_60: JP1.60 JP1B.20 | length 697.1
  Top Layer w7: JP1B.20 1141.73,2909.45 1204.72,2846.46 1307.09,2846.46 1452.95,2700.59 JP1.60
JP3_61: JP1.61 JP1B.21 | length 978.4
  Top Layer w7: v1(1421.26,2322.83) 1421.46,2322.64 JP1.61
  Bottom Layer w7: JP1B.21 1102.36,3031.5 1102.36,2708.66 1421.26,2389.76 v1(1421.26,2322.83)
JP3_62: JP1.62 JP1B.22 | length 721.3
  Top Layer w7: JP1B.22 1062.99,2917.32 1161.42,2818.9 1271.65,2818.9 1421.46,2669.09 JP1.62
JP3_63: JP1.63 JP1B.23 | length 998
  Top Layer w7: v1(1389.76,2299.21) 1389.96,2299.02 JP1.63
  Bottom Layer w7: JP1B.23 1023.62,3031.5 1023.62,2755.91 1389.76,2389.76 v1(1389.76,2299.21)
JP3_64: JP1.64 JP1B.24 | length 757
  Top Layer w7: JP1B.24 984.25,2921.26 1114.17,2791.34 1251.97,2791.34 1389.96,2653.35 JP1.64
JP3_65: JP1.65 JP1B.25 | length 1017.5
  Top Layer w7: v1(1358.27,2322.83) 1358.46,2322.64 JP1.65
  Bottom Layer w7: JP1B.25 944.88,3031.5 944.88,2803.15 1358.27,2389.76 v1(1358.27,2322.83)
JP3_66: JP1.66 JP1B.26 | length 790.4
  Top Layer w7: JP1B.26 905.51,2929.13 1066.93,2767.72 1228.35,2767.72 1358.46,2637.6 JP1.66
JP3_67: JP1.67 JP1B.27 | length 1037.1
  Top Layer w7: v1(1326.77,2299.21) 1326.97,2299.02 JP1.67
  Bottom Layer w7: JP1B.27 866.14,3031.5 866.14,2842.52 1326.77,2381.89 v1(1326.77,2299.21)
JP3_68: JP1.68 JP1B.28 | length 833.1
  Top Layer w7: JP1B.28 826.77,2921.26 1003.94,2744.09 1204.72,2744.09 1326.97,2621.85 JP1.68
JP3_69: JP1.69 JP1B.29 | length 1068.2
  Top Layer w7: v1(1295.28,2322.83) 1295.47,2322.64 JP1.69
  Bottom Layer w7: JP1B.29 787.4,3031.5 787.4,2870.08 956.69,2700.79 976.38,2700.79 1295.28,2381.89 v1(1295.28,2322.83)
JP3_70: JP1.70 JP1B.30 | length 880.3
  Top Layer w7: JP1B.30 748.03,2913.39 944.88,2716.54 1192.91,2716.54 1295.47,2613.98 JP1.70
JP3_71: JP1.71 JP1B.31 | length 1099.3
  Top Layer w7: v1(1263.78,2299.21) 1263.98,2299.02 JP1.71
  Bottom Layer w7: JP1B.31 708.66,3031.5 708.66,2889.76 929.13,2669.29 968.5,2669.29 1263.78,2374.02 v1(1263.78,2299.21)
JP3_72: JP1.72 JP1B.32 | length 913.7
  Top Layer w7: JP1B.32 669.29,2921.26 905.51,2685.04 1177.17,2685.04 1263.98,2598.23 JP1.72
JP3_73: JP1.73 JP1B.33 | length 1148.9
  Top Layer w7: v1(1232.28,2322.83) 1232.48,2322.64 JP1.73
  Bottom Layer w7: JP1B.33 629.92,3031.49 629.92,2881.89 870.08,2641.73 960.63,2641.73 1232.28,2370.08 v1(1232.28,2322.83)
JP3_74: JP1.74 JP1B.34 | length 947.1
  Top Layer w7: JP1B.34 590.55,2917.32 846.46,2661.42 1141.73,2661.42 1232.48,2570.67 JP1.74
JP3_75: JP1.75 JP1B.35 | length 1205.3
  Top Layer w7: v1(1200.79,2299.21) 1200.98,2299.02 JP1.75
  Bottom Layer w7: JP1B.35 551.18,3031.5 551.18,2858.27 795.28,2614.17 948.82,2614.17 1200.79,2362.2 v1(1200.79,2299.21)
JP3_76: JP1.76 JP1B.36 | length 985.2
  Top Layer w7: JP1B.36 511.81,2913.39 791.34,2633.86 1118.11,2633.86 1200.98,2550.98 JP1.76
JP3_77: JP1.77 JP1B.37 | length 1312.5
  Top Layer w7: v1(1169.29,2322.83) 1169.49,2322.64 JP1.77
  Bottom Layer w7: JP1B.37 472.44,3031.5 472.44,2748.03 637.8,2582.68 940.94,2582.68 1169.29,2354.33 v1(1169.29,2322.83)
JP3_79: JP1.79 JP1B.39 | length 1329.8
  Top Layer w7: v1(1137.8,2299.21) 1137.99,2299.02 JP1.79
  Bottom Layer w7: JP1B.39 393.7,3031.5 393.7,2795.28 625.98,2562.99 925.2,2562.99 1137.8,2350.39 v1(1137.8,2299.21)
JTAG_TCK: JP1.5 JP3.6 | length 2288.3
  Top Layer w7: JP3.6 410.71,1519.68 523.62,1519.68 539.37,1535.43 1669.29,1535.43 2303.35,2169.49 JP1.5
JTAG_TDI: JP1.9 JP3.10 | length 2153.1
  Top Layer w7: JP3.10 410.71,1677.17 1736.22,1677.17 2240.35,2181.3 JP1.9
JTAG_TDO: JP1.8 JP3.8 | length 2830.9
  Top Layer w7: v1(555.12,1484.25) 590.55,1519.68 1732.28,1519.68 2488.19,2275.59 2488.19,2318.9 2393.7,2413.39 2295.28,2413.39 2271.85,2436.81 JP1.8
  Bottom Layer w7: JP3.8 411.65,1519.68 480.31,1519.68 515.75,1484.25 v1(555.12,1484.25)
JTAG_TMS: JP1.7 JP3.4 | length 2460.8
  Top Layer w7: JP3.4 318.9,1454.96 318.9,1574.8 342.52,1598.43 1692.91,1598.43 2271.85,2177.36 JP1.7
VREF_BANK1: JP1.10 JP1A.10 | length 1367.7
  Top Layer w12: JP1.10 2240.35,2571.06 2350.39,2681.1 3035.43,2681.1 JP1A.10
pads on no net: JP1.3 JP1.12 JP1.81 JP1.82 JP1A.3 JP1A.5 JP1A.7 JP1A.8 JP1A.9 JP1A.12 JP2.81 JP2.82 JP3.12 JP3.14 P1.3

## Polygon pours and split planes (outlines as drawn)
DGND on Bottom Layer "Bottom Layer-No Net" (solid, remove dead copper, pour order 1000): 0,3149.61 0,0 4724.41,0 4724.41,3149.61

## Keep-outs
Keep-Out Layer:
  the board outline again, w7.01

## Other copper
Top Layer:
  region net +VDC: 4232.28,633.86 4090.55,633.86 3854.33,397.64 3586.61,397.64 3370.08,614.17 2295.28,614.17 2295.28,574.8 2421.26,448.82 3173.23,448.82 3401.57,220.47 3437.01,220.47 3464.57,192.91 3464.57,133.86 3480.32,118.11 4110.24,118.11 4295.28,303.15 4295.28,570.87

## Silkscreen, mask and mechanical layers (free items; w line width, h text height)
Top Overlay:
  lines w7.99: 748.03,1181.1 748.03,590.55 1338.58,590.55 ; 748.03,1968.5 748.03,2559.06 1338.58,2559.06 ; 3110.24,590.55 3700.79,590.55 3700.79,1181.1 ; 3110.24,2559.06 3700.79,2559.06 3700.79,1968.5
  text "DGND" at 3842.52,2992.13 h40
  text "VCCO0" at 2027.56,2826.77 h30
  text "DGND" at 208.66,2751.97 h40
  text "+3.3V" at 3755.91,2744.09 h40
  text "BRK6110" at 4197.74,2062.43 h40 r90
  text "20100408" at 4276.48,2062.43 h40 r90
  text "XILINX JTAG" at 566.93,1767.72 h40 r270
  text "TDI" at 208.66,1618.11 h40
  text "TDO" at 196.85,1539.37 h40
  text "TCK" at 196.85,1460.63 h40
  text "TMS" at 196.85,1381.89 h40
  text "+3.3V" at 125.98,1303.15 h40
  text "DGND" at 3779.53,992.13 h40
  text "+1.2V" at 3897.64,464.57 h30
  text "+1.8VDD" at 3370.08,460.63 h30
  text "DGND" at 228.35,417.32 h40
  text "VCCO0" at 2066.93,303.15 h30
  text "+VDC" at 4141.89,196.85 h30
Top Solder:
  the board outline again, w1
Mechanical 2:
  the board outline again, w8
Drill Drawing:
  lines w10: 3308.03,-677.68 6703.78,-677.68 ; 3308.03,-503.68 6703.78,-503.68 ; 3248.03,-1101.48 ccw(c3304.03,-1101.48) 3304.03,-1157.48 6707.78,-1157.48 ccw(c6707.78,-1101.48) 6763.78,-1101.48 6763.78,-422.14 ccw(c6707.78,-422.14) 6707.78,-366.14 3304.03,-366.14 ccw(c3304.03,-422.14) 3248.03,-422.14 3248.03,-1101.48
  text ".LEGEND" at 4929.13,27.56 h50
  text "NOTES" at 64.15,-342.9 h50
  text "1. MATERIAL SELECTION:" at 64.15,-442.9 h50
  text "Layer Stack Up Detail for: EVB5010.PcbDoc" at 3308.03,-470.71 h51
  text "2-LAYER, 370HR, 0.062\" +/- 0.005 THICK" at 189.15,-517.9 h50
  text "Layer" at 3308.03,-568.68 h40
  text "Gerber" at 4116.1,-568.68 h40
  text "Copper" at 4709.17,-568.68 h40
  text "Dielectric" at 5367.55,-568.68 h40
  text "Dielectric" at 6053.93,-568.68 h40
  text "SURFACE FINISH: ENIG (ELECTROLESS NICKEL, IMMERSION GOLD)" at 189.15,-592.9 h50
  text "Name" at 3308.03,-648.68 h40
  text "Document" at 4116.1,-648.68 h40
  text "Thickness" at 4709.17,-648.68 h40
  text "Height" at 5367.55,-648.68 h40
  text "Material" at 6053.93,-648.68 h40
  text "2. SOLDER RESIST: GREEN LPI" at 64.15,-717.9 h50
  text "Top Layer" at 3308.03,-801.38 h56
  text "(.GTL)" at 4116.1,-801.38 h56
  text "1.4mil" at 4709.17,-801.38 h56
  text "3. SILKSCREEN: WHITE / DO NOT REMOVE OVER TENTED VIAS." at 64.15,-842.9 h50
  text "62mil" at 5367.55,-880.51 h56
  text "FR-4" at 6053.93,-880.51 h56
  text "Bottom Layer" at 3308.03,-959.65 h56
  text "(.GBL)" at 4116.1,-959.65 h56
  text "1.4mil" at 4709.17,-959.65 h56
  text "4. LOT CODE IDENTIFICATION: ADD TO SILKSCREEN" at 64.15,-967.9 h50
  text "5. DRILL SIZES ARE FINISHED SIZE AFTER PLATING." at 64.15,-1092.9 h50
  text "6. ELECTRICAL BARE BOARD TEST REQUIRED" at 64.15,-1217.9 h50
  text "7. FABRICATE TO MEET EU ROHS DIRECTIVE" at 64.15,-1342.9 h50
  text "8. PANELIZATION:" at 64.15,-1463.33 h50
  text "2-PIECES PER PANEL" at 189.15,-1538.33 h50
  text "0.1-IN RAILS ON ALL SIDES" at 189.15,-1613.33 h50
  text "0.1-IN TAB ROUTING WITH MOUSE-BITES FOR BOARD SEPARATION" at 189.15,-1688.33 h50

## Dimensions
0,0 to 4724.41,0 on Mechanical 1
118.11,118.11 to 4606.3,118.11 on Mechanical 1
0,0 to 0,3149.61 on Mechanical 1
118.11,3031.5 to 118.11,118.11 on Mechanical 1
